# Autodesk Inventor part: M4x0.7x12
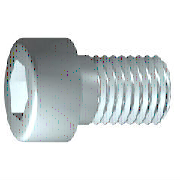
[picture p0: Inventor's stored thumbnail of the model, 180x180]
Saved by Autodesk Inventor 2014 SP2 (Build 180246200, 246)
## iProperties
IsCustomPart: 0
Created: 2016-05
Part Number: M4x0.7x12
Material: 강, 연강
Description: 6각머리 태핑 나사
Document SubType Name: Modeling
Standard: KS B 1003
Designer: mduedu
Standards Organization: KS
Language: ko-KR
Size Designation: M 4 x 12
Categories: <MemberInstance><Categories><Category DisplayName="조임쇠" InternalName="e4da775c-781d-43d5-af7c-5136215cf5a6" Mnemonic="FSTN"><Category DisplayName="볼트" InternalN
Density: 1 g/cm^3
Appearance: 연마 - 진회색
Author: mduedu
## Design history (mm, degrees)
sketch "스케치1"
  geometry: L1 (-1, 0)-(12, 0); L2 (12, 0)-(12, 2); L3 (12, 2)-(1.75, 2); L4 (1.75, 2)-(1.32, 2); L5 (1.32, 2)-(0, 2); L6 (0, 2)-(0, 3.5); L7 (0, 3.5)-(-4, 3.5); L8 (-4, 3.5)-(-4, 1.732); L9 (-4, 1.732)-(-2, 1.732); L10 (-2, 1.732)-(-1, 0); L11 (-7.2, 0)-(15.2, 0) reference; L12 (0, -0.7)-(0, 4.2) reference; L13 (1.75, 2)-(0, 2)
  constraints: 22 end point, 6 parallel, 2 collinear, 2 perpendicular, 1 horizontal, 1 point on line
  dimensions: "d1" = 10.25 distance from line of L3.end L2 (= GEL); "d2" = 0.42952 distance of L4.end L3.end (computed from GAL); "d3" = 4 distance between parallel lines of L8 L6 (= KOH); "d4" = 2 distance of L8.end L9.end (= INTI); "d5" = 60 deg angle of L10 L1; "d6" = 4 diameter of L3 L1 (= GD); "d7" = 4 diameter of L5 L1 (= BDM); "d8" = 3.4641 diameter of L9 L1 (= 1.1547 x SW); "d9" = 7 diameter of L7 L1 (= KOD); "d26" = 12 distance between parallel lines of L12 L2 (= NLG)
revolve "본체" sketch "스케치1" stored, may be unused: angle "d10" = 90 deg
sketch "스케치2"
  geometry: L1 (0, -4.9)-(0, 4.9) reference; L2 (-4.9, 0)-(4.9, 0) reference; L3 (1.732, 0)-(0.866, -1.5); L4 (0.866, -1.5)-(-0.866, -1.5); L5 (-0.866, -1.5)-(-1.732, 0); L6 (-1.732, 0)-(-0.866, 1.5); L7 (-0.866, 1.5)-(0.866, 1.5); L8 (0.866, 1.5)-(1.732, 0); 2 further points
  constraints: 12 end point, 1 coincident, 1 horizontal alignment, 1 point on line, 12 other
extrude "슬롯" join sketch "스케치2" stored distance "d11" = 10; taper "d12" = 0 deg
workplane "Work Plane1"
fillet "Fillet2" dims "d30" = 0.1 (= R)
body "Solid1"
fillet "모깎기1" dims "d17" = 0.4 (= RR)
feature "스레드" dims "d13" = 10.25 (= GEL), "d14" = 0
chamfer "모따기1" distance "d15" = 0.42941 (= -0.5 x SPD + 0.5 x GD); stored, may be unused: second distance "d16" = 0.42941 (= GUL), angle "d27" = 45 deg
other parameters: "GD" = 4 (= NND) [user parameter; used in 2 equation terms], "NLG" = 12 [user parameter; used in 1 equation term], "GEL" = 10.25 [user parameter; used in 2 equation terms], "KOD" = 7 [user parameter; used in 1 equation term], "KOH" = 4 [user parameter; used in 1 equation term], "INTI" = 2 [user parameter; used in 1 equation term], "GAL" = 0.42941 (= 0.61345 x PTC) [user parameter; used in 1 equation term], "GUL" = 0.42941 (= 0.61345 x PTC) [user parameter; used in 1 equation term], "BDM" = 4 (= NND) [user parameter; used in 1 equation term], "SW" = 3 [user parameter; used in 2 equation terms], "RR" = 0.4 [user parameter; used in 1 equation term], "SPD" = 3.14117 (= NND - 1.2269 x PTC) [user parameter; used in 1 equation term], "d19" = 0, "d28" = 0, "d29" = 0, "R" = 0.1 [user parameter; used in 1 equation term], "PHH" = 0.2 [user parameter], "GD1" = 3.14117 (= THREADDIA - 1.2269 x PTC) [user parameter], "THREADDIA" = 4 [user parameter; used in 1 equation term], "FAWI" = 45 deg [user parameter], "TPU" = 14.28571 (computed from PTC) [user parameter], "PTC" = 0.7 [user parameter; used in 5 equation terms], "NND" = 4 [user parameter; used in 3 equation terms], "TOA" = 30 deg [user parameter], "E0" = 3.465 (= 1.155 x SW) [user parameter]
